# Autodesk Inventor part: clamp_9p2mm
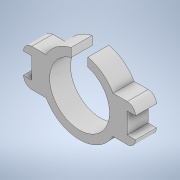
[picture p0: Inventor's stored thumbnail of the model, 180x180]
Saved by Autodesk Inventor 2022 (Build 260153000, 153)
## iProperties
Created: 2022-12
Part Number: clamp_9p2mm
Material: Generic
Document SubType Name: Modeling
Designer: suerfu
Density: 1 g/cm^3
Appearance: Default
Author: suerfu
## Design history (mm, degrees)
sketch "Sketch1" dims "d1" = 11.64 (computed from d0)
  geometry: L1 (-5.599, 1.587)-(-7.239, 1.587); L2 (-7.239, 1.587)-(-7.239, -1.588); L3 (-7.239, -1.588)-(-5.599, -1.588); L4 (-5.599, -1.588)-(-5.599, 1.587); L5 (5.599, 1.587)-(7.239, 1.587); L6 (7.239, 1.587)-(7.239, -1.588); L7 (7.239, -1.588)-(5.599, -1.587); L8 (5.599, -1.587)-(5.599, 1.587); L9 (-1.27, 5.68)-(1.27, 5.68); L10 (1.27, 5.68)-(1.27, 4.369); L11 (1.27, 4.369)-(-1.27, 4.369); L12 (-1.27, 4.369)-(-1.27, 5.68); L13 (-7.256, 2.84)-(-5.08, 2.84); L14 (-5.08, 2.84)-(-5.08, 1.587); L15 (-5.08, 1.587)-(-8.509, 1.588); L16 (-8.509, 1.588)-(-8.509, 2.858); L17 (-7.241, -2.846)-(-5.077, -2.846); L18 (-5.077, -2.846)-(-5.077, -1.579); L19 (-5.077, -1.579)-(-8.507, -1.579); L20 (5.082, 2.837)-(7.248, 2.837); L21 (8.5, 1.584)-(5.082, 1.584); L22 (5.082, 1.584)-(5.082, 2.837); L23 (7.248, -2.832)-(5.084, -2.832); L24 (5.084, -2.832)-(5.084, -1.579); L25 (5.084, -1.579)-(8.5, -1.579); A1 r 4.55 centre (0, 0) between (-1.27, 4.369) and (1.27, 4.369); A2 r 1.253 centre (-7.256, 1.587) between (-7.256, 2.84) and (-8.509, 1.588); A3 r 1.267 centre (-7.241, -1.579) between (-8.507, -1.579) and (-7.241, -2.846); A4 r 1.253 centre (7.248, 1.584) between (8.5, 1.584) and (7.248, 2.837); A5 r 1.253 centre (7.248, -1.579) between (7.248, -2.832) and (8.5, -1.579); 13 further points
  constraints: 50 end point, 11 parallel, 11 point on circle, 7 horizontal, 7 point on line, 6 perpendicular, 5 centre point, 4 tangent, 3 equal length, 2 coincident, 1 collinear, 12 other
  dimensions: "d0" = 9.1 diameter of A1; "d2" = 3.175 distance of L1.end L2.end; "d5" = 2.54 distance of L9.start L9.end; "d11" = 14.478 distance between parallel lines of L6 L2; "d12" = 1.27 distance of L15.end L16.end; "d13" = 1.27 distance between parallel lines of L2 L16
extrude "Extrusion1" new body sketch "Sketch1" distance "d6" = 3.175; taper "d7" = 0 deg
body "Solid1"
